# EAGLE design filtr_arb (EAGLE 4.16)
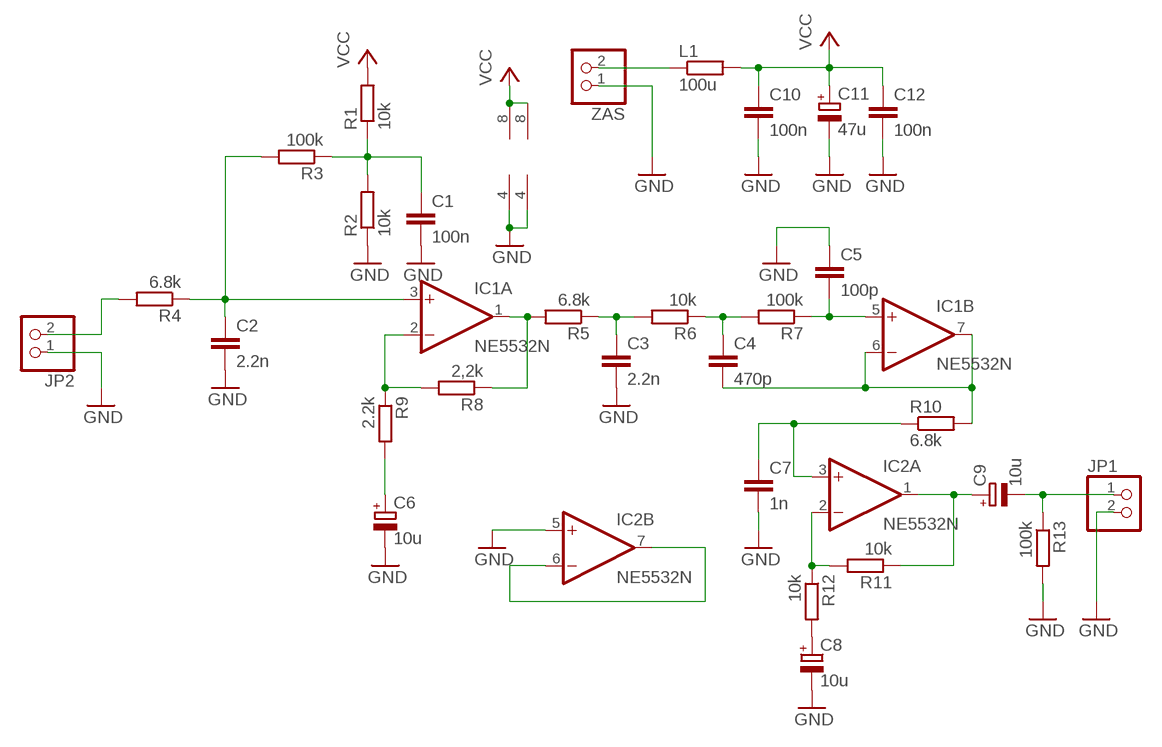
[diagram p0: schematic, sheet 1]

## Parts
C1  100n  C5/2.5  [C5B2.5]
C2  2.2n  C2.5/2  [C2.5-2]
C3  2.2n  C2.5/2  [C2.5-2]
C4  470p  C2.5/2  [C2.5-2]
C5  100p  C2.5/2  [C2.5-2]
C6  10u  CPOL-EUE2-4  [E2-4]
C7  1n  C2.5/2  [C2.5-2]
C8  10u  CPOL-EUE2-4  [E2-4]
C9  10u  CPOL-EUE2-4  [E2-4]
C10  100n  C5/2.5  [C5B2.5]
C11  47u  CPOL-EUE2-4  [E2-4]
C12  100n  C5/2.5  [C5B2.5]
IC1  NE5532N  [DIL08]
IC2  NE5532N  [DIL08]
JP1  PINHD-1X2  [1X02]
JP2  PINHD-1X2  [1X02]
L1  100u  R-EU_0204/5  [0204/5]
R1  10k  R-EU_0204/7  [0204/7]
R2  10k  R-EU_0204/7  [0204/7]
R3  100k  R-EU_0204/7  [0204/7]
R4  6.8k  R-EU_0204/7  [0204/7]
R5  6.8k  R-EU_0204/7  [0204/7]
R6  10k  R-EU_0204/7  [0204/7]
R7  100k  R-EU_0204/7  [0204/7]
R8  2,2k  R-EU_0204/7  [0204/7]
R9  2.2k  R-EU_0204/7  [0204/7]
R10  6.8k  R-EU_0204/7  [0204/7]
R11  10k  R-EU_0204/7  [0204/7]
R12  10k  R-EU_0204/7  [0204/7]
R13  100k  R-EU_0204/7  [0204/7]
ZAS  PINHD-1X2  [1X02]

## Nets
GND: C1.2 C2.2 C3.2 C5.1 C6.- C7.2 C8.- C10.2 C11.- C12.2 IC1.4(P:V-) IC2.4(P:V-) IC2.5(B:+IN) JP1.2 JP2.1 R2.1 R13.2 ZAS.1
N$1: C1.1 R1.1 R2.2 R3.1
N$2: C2.1 IC1.3(A:+IN) R3.2 R4.1
N$3: IC1.1(A:OUT) R5.2 R8.1
N$4: C3.1 R5.1 R6.2
N$5: C4.1 R6.1 R7.2
N$6: C5.2 IC1.5(B:+IN) R7.1
N$7: C7.1 IC2.3(A:+IN) R10.1
N$8: C4.2 IC1.6(B:-IN) IC1.7(B:OUT) R10.2
N$9: IC1.2(A:-IN) R8.2 R9.1
N$10: C6.+ R9.2
N$11: C9.+ IC2.1(A:OUT) R11.1
N$12: IC2.6(B:-IN) IC2.7(B:OUT)
N$13: IC2.2(A:-IN) R11.2 R12.1
N$14: C8.+ R12.2
N$15: JP2.2 R4.2
N$16: L1.1 ZAS.2
N$17: C9.- JP1.1 R13.1
VCC: C10.1 C11.+ C12.1 IC1.8(P:V+) IC2.8(P:V+) L1.2 R1.2

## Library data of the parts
C1-C5 C7 C10 C12 = capacitor-wima:C: CAPACITOR
C6 C8 C9 C11 = rcl:CPOL-EU: POLARIZED CAPACITOR, European symbol
IC1 IC2 = linear:NE5532: AUDIO AMPLIFIER
JP1 JP2 ZAS = pinhead:PINHD-1X2: PIN HEADER
L1 R1-R13 = rcl:R-EU_: RESISTOR, European symbol

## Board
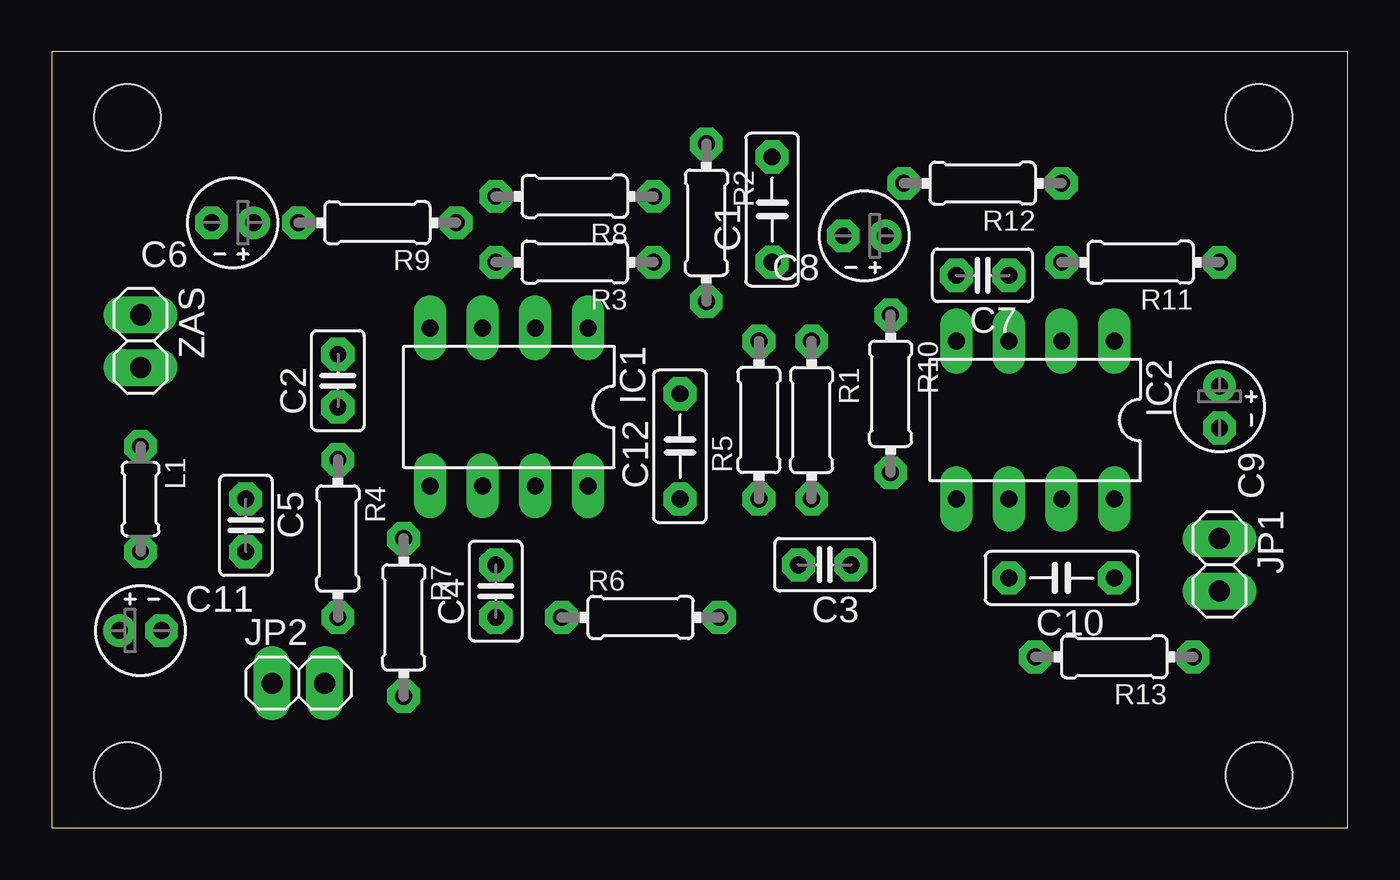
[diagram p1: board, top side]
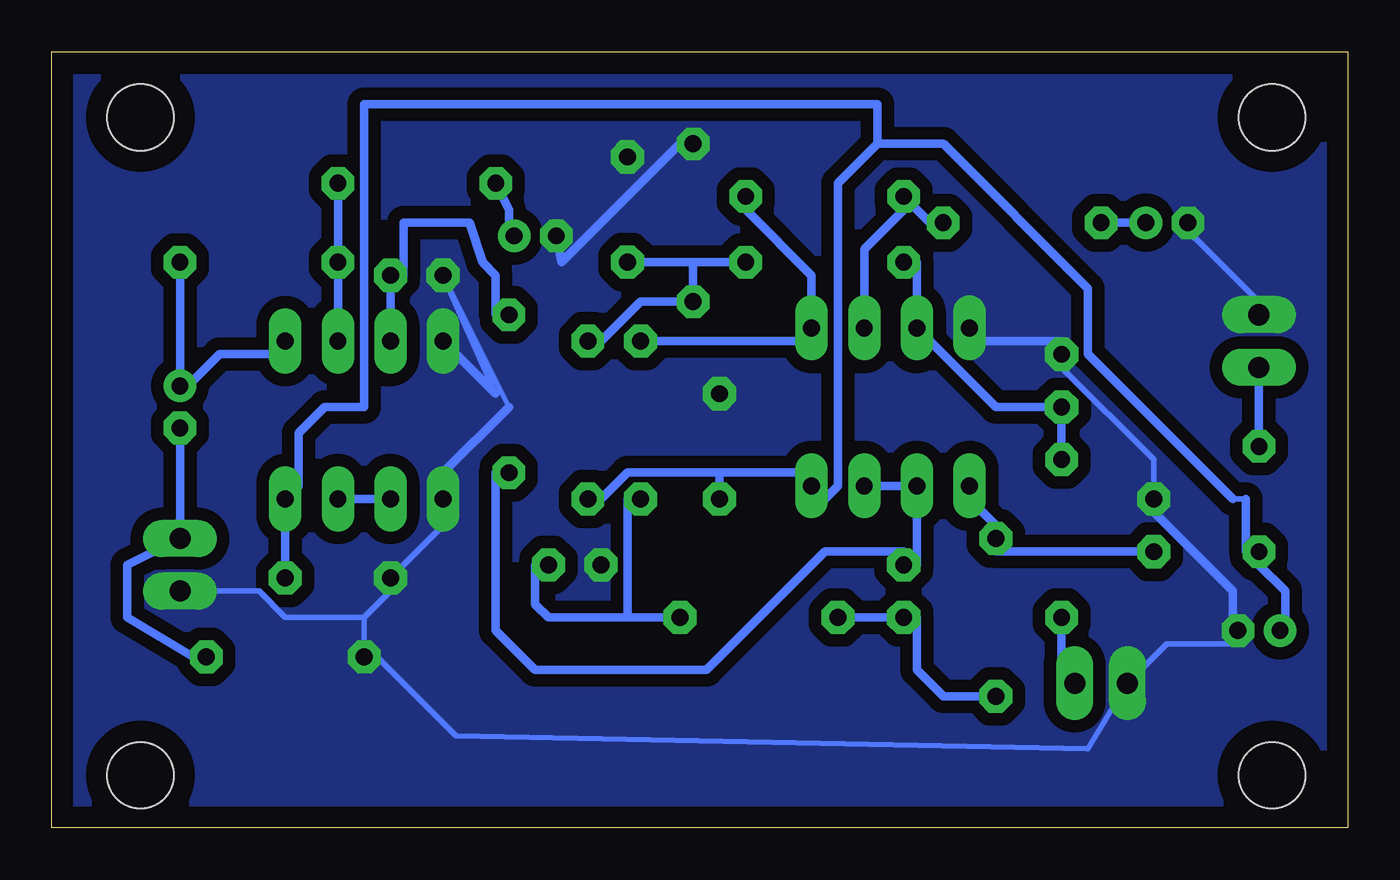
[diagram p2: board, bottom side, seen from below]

Size 62.53 x 37.45 mm. Coordinates in mm from the lower left corner, seen from the top.
Outline: 0,0 62.53,0 62.53,37.45 0,37.45 0,0
Copper layers (1*16): Top 0.035mm / dielectric 1.5mm / Bottom 0.035mm
Design rules "default": minimum track width 10mil, minimum drill 24mil, track to track 8mil, track to pad 8mil, pad to pad 8mil, via to via 8mil, smd to smd 8mil, copper to edge 40mil, drill to drill 8mil, minimum pad ring 15mil, minimum via ring 8mil, stop-mask expansion 4mil, vias tented up to drill 0mil, thermal gap 10mil
Holes 3.2 mm at 3.64,34.28 3.64,2.54 58.25,2.54 58.25,34.28

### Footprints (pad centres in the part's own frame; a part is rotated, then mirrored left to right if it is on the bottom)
C5B2.5 = drill 0.813 pad 1.6 octagon: 1 -2.54,0; 2 2.54,0
C2.5-2 = drill 0.813 pad 1.6 octagon: 1 -1.27,0; 2 1.27,0
E2-4 = drill 0.813 pad 1.27 round: + -1.016,0 | drill 0.813 pad 1.27 octagon: - 1.016,0
DIL08 = drill 0.813 long: 1 -3.81,-3.81; 2 -1.27,-3.81; 3 1.27,-3.81; 4 3.81,-3.81; 5 3.81,3.81; 6 1.27,3.81; 7 -1.27,3.81; 8 -3.81,3.81
1X02 = drill 1.016 long: 1 -1.27,0; 2 1.27,0
0204/5 = drill 0.813 octagon: 1 -2.54,0; 2 2.54,0
0204/7 = drill 0.813 octagon: 1 -3.81,0; 2 3.81,0

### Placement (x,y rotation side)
C1  34.76,29.84 90 top
C2  13.8,21.59 90 top
C3  37.3,12.7 180 top
C4  21.42,11.43 90 top
C5  9.36,14.6 270 top
C6  8.73,29.2 180 top
C7  44.92,26.66 180 top
C8  39.2,28.57 180 top
C9  56.35,20.32 270 top
C10  48.73,12.06 180 top
C11  4.28,9.52 0 top
C12  30.31,18.41 90 top
IC1  22.06,20.32 180 top
IC2  47.46,19.68 180 top
JP1  56.35,12.7 270 top
JP2  11.9,6.98 0 top
L1  4.28,15.87 270 top
R1  36.66,19.68 270 top
R2  31.59,29.2 270 top
R3  25.23,27.3 180 top
R4  13.8,13.96 270 top
R5  34.12,19.68 90 top
R6  28.41,10.16 0 top
R7  16.98,10.16 270 top
R8  25.23,30.48 180 top
R9  15.71,29.2 180 top
R10  40.48,20.95 270 top
R11  52.54,27.3 180 top
R12  44.92,31.11 180 top
R13  51.27,8.25 180 top
ZAS  4.28,23.49 270 top

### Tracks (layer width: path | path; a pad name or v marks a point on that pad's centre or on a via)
GND
  Bottom 0.254: 9.36,15.23 C5.1 9.36,17.77 13.8,22.22 C2.2 | 5.55,10.16 C11.- 5.55,8.89 8.73,8.89 JP2.1 12.54,3.8 43.02,4.44 46.83,8.25 R13.2 47.46,10.16 | 17.62,23.49 IC1.4 | C2.2 13.8,23.49 | 7.46,28.57 4.28,25.4 ZAS.1 | C2.2 13.17,22.86 | R2.1 32.22,33.02 | 41.11,20.95 C7.2 40.48,20.32 | 47.46,10.16 46.19,11.43 C10.2 43.65,14.6 | 47.46,10.16 51.27,10.16 52.54,11.43 JP1.2
  Bottom 0.406: 9.36,15.23 5.55,11.43 5.55,10.16 | 13.8,23.49 17.62,23.49 | 7.46,28.57 C6.- | 32.22,33.02 37.94,27.3 C8.- | 41.11,20.95 IC2.4 | 43.65,14.6 IC2.5 43.65,17.14 40.48,20.32
  pour Bottom (isolate 0.61, no thermals): 1.11,36.19 1.11,0.63 61.43,0.63 61.43,36.19
N$1
  Bottom 0.254: 36.03,23.49 R1.1
  Bottom 0.406: 36.03,23.49 34.12,25.4 R2.2 31.59,27.3 | R3.1 31.59,27.3 | 31.59,27.3 C1.1
N$2
  Bottom 0.254: 20.79,27.3 R3.2
  Bottom 0.406: R4.1 C2.1 16.98,20.32 IC1.3 20.79,27.3
N$3
  Bottom 0.254: IC1.1 26.51,23.49
  Bottom 0.406: 26.51,23.49 R5.2 | R8.1 29.05,29.84 25.87,26.66 IC1.1
N$4
  Bottom 0.406: 34.76,10.16 38.57,10.16 39.2,10.79 39.2,12.7 C3.1 | R6.2 34.76,10.16 | 34.76,10.16 34.76,15.87 R5.1
N$5
  Bottom 0.254: 20.79,10.16 C4.1
  Bottom 0.406: 20.79,10.16 20.79,7.62 19.52,6.35 R7.2 | C4.1 R6.1
N$6
  Bottom 0.406: IC1.5 18.25,15.87 16.98,14.6 R7.1 16.98,13.33 C5.2
N$7
  Bottom 0.254: R10.1 41.11,24.76 | 45.56,26.66 C7.1
  Bottom 0.406: C7.1 IC2.3 | 41.11,24.76 41.11,26.66 41.74,27.3 42.38,29.2 45.56,29.2 45.56,26.66
N$8
  Bottom 0.254: 41.11,17.14 R10.2
  Bottom 0.406: IC1.7 IC1.6 20.79,12.7 C4.2 21.42,13.33 25.23,13.33 30.95,7.62 39.2,7.62 41.11,9.52 41.11,17.14
N$9
  Bottom 0.254: R9.1 20.16,29.2 | R8.2 21.42,29.84
  Bottom 0.406: 20.16,29.2 R8.2 | 21.42,29.84 23.33,27.94 IC1.2
N$10
  Bottom 0.406: C6.+ R9.2
N$11
  Bottom 0.254: 55.72,21.59 C9.+
  Bottom 0.406: 55.72,21.59 54.45,22.86 51.91,22.86 IC2.1 | C9.+ R11.1
N$12
  Bottom 0.406: IC2.6 IC2.7
N$13
  Bottom 0.406: IC2.2 R11.2 R12.1
N$14
  Bottom 0.254: C8.+ 40.48,28.57
  Bottom 0.406: 40.48,28.57 40.48,29.84 R12.2
N$15
  Bottom 0.406: R4.2 13.8,7.62 JP2.2
N$16
  Bottom 0.406: L1.1 ZAS.2
N$17
  Bottom 0.254: R13.1 55.72,8.25
  Bottom 0.406: 55.72,8.25 58.89,10.16 58.89,12.7 JP1.1 C9.-
VCC
  Bottom 0.254: IC1.8 26.51,17.14 | C11.+ 3.01,10.16 | 4.91,15.87 5.55,15.87 | L1.2 4.91,13.33
  Bottom 0.406: 26.51,17.14 30.31,17.14 | 30.31,17.14 34.76,17.14 36.03,15.87 R1.2 | 30.31,17.14 C12.1 | 3.01,10.16 3.01,11.43 4.28,12.7 L1.2 | C10.1 IC2.8 50.64,16.5 50.64,19.05 49.36,20.32 47.46,20.32 47.46,34.92 22.7,34.92 22.7,33.02 | 4.91,13.33 4.91,15.87 | 5.55,15.87 12.54,22.86 12.54,26.03 19.52,33.02 22.7,33.02 | 22.7,33.02 24.6,31.11 24.6,16.5 25.23,15.87 IC1.8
